// Mitsubishi GX Works2 project: 练习-画三角形(2)   PLC: FX3U/FX3UC

PROGRAM MAIN
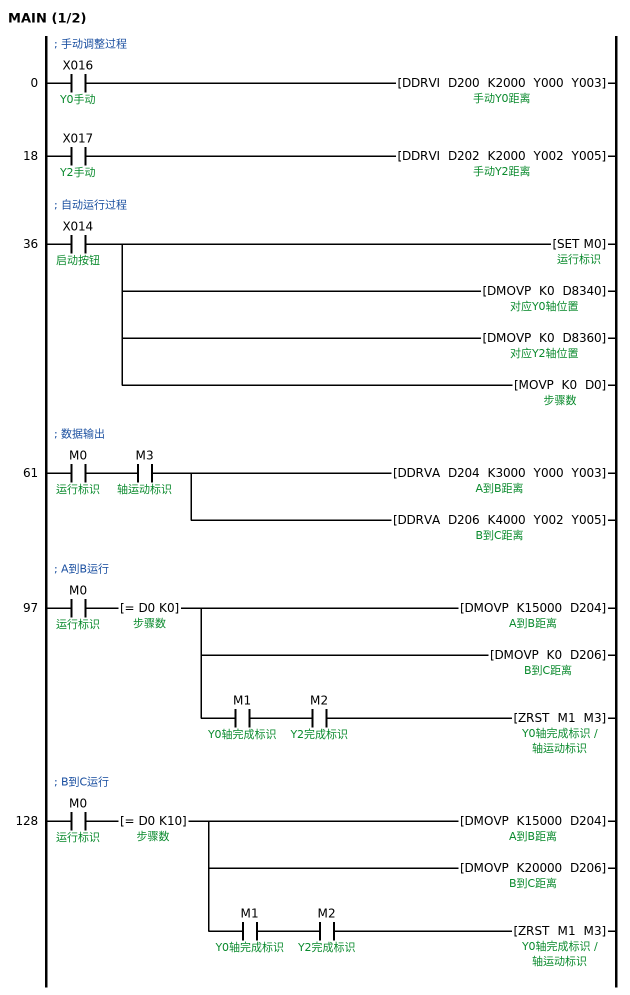
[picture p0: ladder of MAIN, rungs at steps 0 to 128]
; 手动调整过程
0     LD      X016  ; Y0手动
      DDRVI   D200 K2000 Y000 Y003  ; 手动Y0距离
18    LD      X017  ; Y2手动
      DDRVI   D202 K2000 Y002 Y005  ; 手动Y2距离
; 自动运行过程
36    LD      X014  ; 启动按钮
      SET     M0  ; 运行标识
      DMOVP   K0 D8340  ; 对应Y0轴位置
        [note] 定位Y0轴零点
      DMOVP   K0 D8360  ; 对应Y2轴位置
        [note] 定位Y2轴零点
      MOVP    K0 D0  ; 步骤数
; 数据输出
61    LD      M0  ; 运行标识
      AND     M3  ; 轴运动标识
      DDRVA   D204 K3000 Y000 Y003  ; A到B距离
      DDRVA   D206 K4000 Y002 Y005  ; B到C距离
; A到B运行
97    LD      M0  ; 运行标识
      AND=    D0 K0  ; 步骤数
      DMOVP   K15000 D204
      DMOVP   K0 D206
      AND     M1  ; Y0轴完成标识
      AND     M2  ; Y2完成标识
      ZRST    M1 M3
; B到C运行
128   LD      M0  ; 运行标识
      AND=    D0 K10  ; 步骤数
      DMOVP   K15000 D204
      DMOVP   K20000 D206
      AND     M1  ; Y0轴完成标识
      AND     M2  ; Y2完成标识
      ZRST    M1 M3
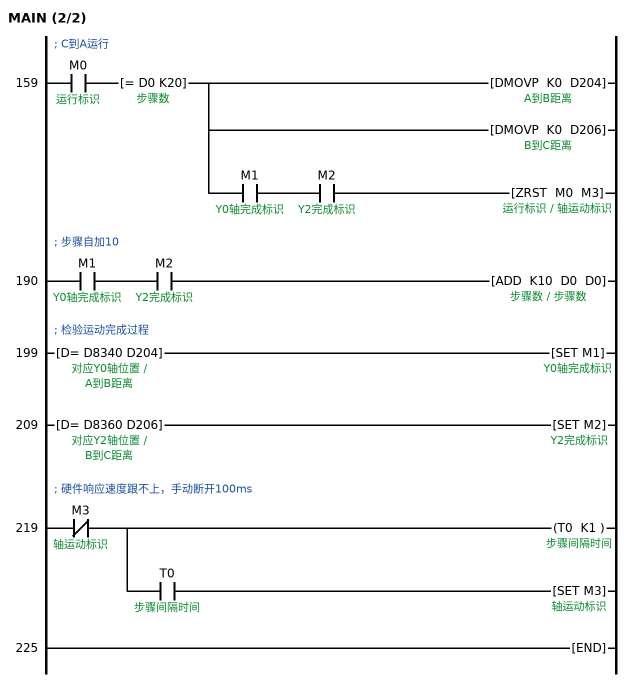
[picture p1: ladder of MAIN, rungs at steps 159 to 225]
; C到A运行
159   LD      M0  ; 运行标识
      AND=    D0 K20  ; 步骤数
      DMOVP   K0 D204
      DMOVP   K0 D206
      AND     M1  ; Y0轴完成标识
      AND     M2  ; Y2完成标识
      ZRST    M0 M3
; 步骤自加10
190   LD      M1  ; Y0轴完成标识
      AND     M2  ; Y2完成标识
      ADD     K10 D0 D0
; 检验运动完成过程
199   LDD=    D8340 D204  ; 对应Y0轴位置 / A到B距离
      SET     M1  ; Y0轴完成标识
209   LDD=    D8360 D206  ; 对应Y2轴位置 / B到C距离
      SET     M2  ; Y2完成标识
; 硬件响应速度跟不上，手动断开100ms
219   LDI     M3  ; 轴运动标识
      OUT     T0 K1  ; 步骤间隔时间
        [note] 每一步之间断开100ms
      AND     T0  ; 步骤间隔时间
      SET     M3  ; 轴运动标识
225   END
END_PROGRAM

// device comments not shown above
X015  ; B到C
Y001  ; 方向
D201  ; 零点
D208  ; A到B距离
D210  ; A到B速度
